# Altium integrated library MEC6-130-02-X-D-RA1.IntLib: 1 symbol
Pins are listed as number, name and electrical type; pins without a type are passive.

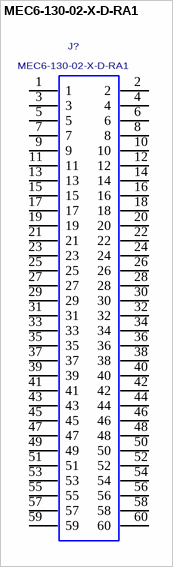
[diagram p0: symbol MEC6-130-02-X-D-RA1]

## MEC6-130-02-X-D-RA1
designator J?
.635mm [.025"] RIGHT ANGLE EDGE CARD ASSEMBLY.; MANUFACTURER: SAMTEC
footprint MEC6-130-02-X-D-RA1
pins: 1, 2, 3, 4, 5, 6, 7, 8, 9, 10, 11, 12, 13, 14, 15, 16, 17, 18, 19, 20, 21, 22, 23, 24, 25, 26, 27, 28, 29, 30, 31, 32, 33, 34, 35, 36, 37, 38, 39, 40, 41, 42, 43, 44, 45, 46, 47, 48, 49, 50, 51, 52, 53, 54, 55, 56, 57, 58, 59, 60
